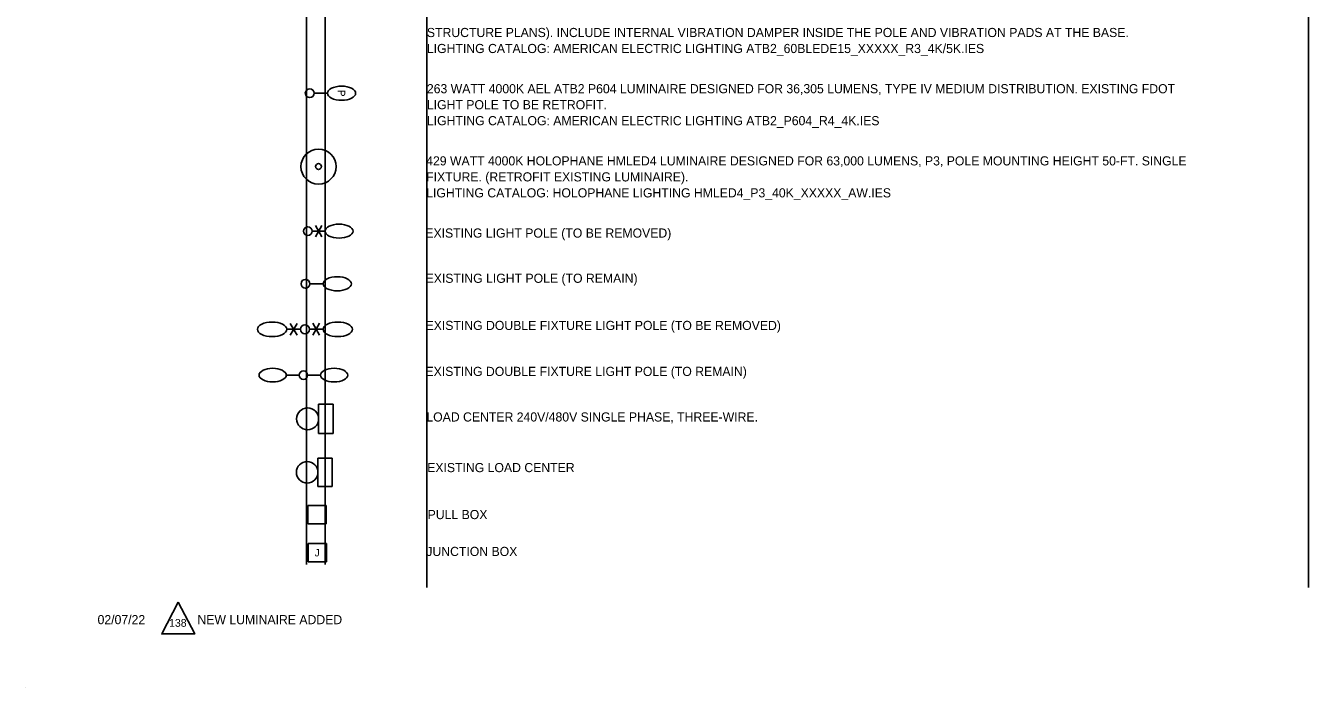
# Model space of a CAD drawing. Extents: x -0.6 to 15.1, y -0.9 to 9.2.
# Drawn here: x -0.55 to 9.27, y -0.9 to 4.17 of the extents above; entities that cross this region are included whole.
import ezdxf

# ---------------------------------------------------------------- set-up
doc = ezdxf.new("R2010")
doc.units = 0
for name, color, linetype in [('ActivePointCell_dp', 7, 'Continuous'), ('AdhocPoint_dp', 7, 'Continuous'), ('Cloud_dp', 7, 'Continuous'), ('JunctBoxA', 7, 'Continuous'), ('LoadCenter', 7, 'Continuous'), ('LoadCenter_ep', 7, 'Continuous'), ('PoleLight', 7, 'Continuous'), ('PoleLight_ep', 7, 'Continuous'), ('PullBox', 7, 'Continuous'), ('TextLabel', 7, 'Continuous'), ('TextMisc', 7, 'Continuous')]:
    doc.layers.add(name, color=color, linetype=linetype)

msp = doc.modelspace()

# ---------------------------------------------------------------- linework, layer by layer
at = {"layer": 'ActivePointCell_dp'}
for p, q in [((2.5213, -0.1347), (2.5213, 8.8406)), ((9.2686, -0.1347), (9.2686, 8.9112)), ((1.7419, 8.8041), (1.7419, 0.0422)), ((1.6003, 8.6424), (1.6003, 0.0422))]:
    msp.add_line(p, q, dxfattribs=at)
at = {"layer": 'AdhocPoint_dp'}
msp.add_line((-0.55, -0.9), (-0.55, -0.9), dxfattribs=at)
at = {"layer": 'Cloud_dp'}
msp.add_lwpolyline([(0.618, -0.2467), (0.4913, -0.4908), (0.7447, -0.4908)], close=True, dxfattribs=at)
at = {"layer": 'LoadCenter'}
for p, q in [((1.6927, 1.0446), (1.6927, 1.2695)), ((1.6927, 1.2695), (1.8051, 1.2695)), ((1.8051, 1.2695), (1.8051, 1.0446)), ((1.8051, 1.0446), (1.6927, 1.0446))]:
    msp.add_line(p, q, dxfattribs=at)
msp.add_circle((1.6083, 1.1571), 0.0843, dxfattribs=at)
at = {"layer": 'LoadCenter_ep'}
for p, q in [((1.6872, 0.6379), (1.6872, 0.8572)), ((1.6872, 0.8572), (1.7968, 0.8572)), ((1.7968, 0.8572), (1.7968, 0.6379)), ((1.7968, 0.6379), (1.6872, 0.6379))]:
    msp.add_line(p, q, dxfattribs=at)
msp.add_circle((1.6049, 0.7476), 0.0822, dxfattribs=at)
at = {"layer": 'PoleLight'}
msp.add_line((1.6584, 3.6517), (1.7598, 3.6517), dxfattribs=at)
for centre, radius in [((1.6246, 3.6517), 0.0338), ((1.6918, 3.0899), 0.1344), ((1.6918, 3.0899), 0.0224)]:
    msp.add_circle(centre, radius, dxfattribs=at)
msp.add_ellipse((1.8679, 3.6517), major_axis=(0.1082, 0), ratio=0.5, dxfattribs=at)
at = {"layer": 'PoleLight_ep'}
for p, q in [((1.6427, 2.5953), (1.7426, 2.5953)), ((1.7176, 2.5521), (1.6677, 2.6386)), ((1.7176, 2.6386), (1.6677, 2.5521)), ((1.6254, 2.192), (1.7268, 2.192)), ((1.4753, 1.7974), (1.5276, 1.8881)), ((1.4753, 1.8881), (1.5276, 1.7974)), ((1.7001, 1.8892), (1.6477, 1.7985)), ((1.7001, 1.7985), (1.6477, 1.8892)), ((1.5528, 1.8433), (1.4481, 1.8433)), ((1.6226, 1.8433), (1.7273, 1.8433)), ((1.5431, 1.492), (1.4451, 1.492)), ((1.6084, 1.492), (1.7063, 1.492))]:
    msp.add_line(p, q, dxfattribs=at)
for centre, radius in [((1.6094, 2.5953), 0.0333), ((1.5916, 2.192), 0.0338), ((1.5877, 1.8433), 0.0349), ((1.5757, 1.492), 0.0326)]:
    msp.add_circle(centre, radius, dxfattribs=at)
for centre, major_axis in [((1.8492, 2.5953), (0.1066, 0)), ((1.835, 2.192), (0.1082, 0)), ((1.3364, 1.8433), (-0.1117, 0)), ((1.839, 1.8433), (0.1117, 0)), ((1.3407, 1.492), (-0.1045, 0)), ((1.8108, 1.492), (0.1045, 0))]:
    msp.add_ellipse(centre, major_axis=major_axis, ratio=0.5, dxfattribs=at)
at = {"layer": 'PullBox'}
for p, q in [((1.6108, 0.3526), (1.6108, 0.4932)), ((1.6108, 0.4932), (1.7514, 0.4932)), ((1.7514, 0.4932), (1.7514, 0.3526)), ((1.7514, 0.3526), (1.6108, 0.3526)), ((1.6115, 0.2018), (1.7522, 0.2018)), ((1.6115, 0.0612), (1.6115, 0.2018)), ((1.7522, 0.2018), (1.7522, 0.0612)), ((1.7522, 0.0612), (1.6115, 0.0612))]:
    msp.add_line(p, q, dxfattribs=at)

# ---------------------------------------------------------------- texts
at = {"layer": 'Cloud_dp'}
msp.add_text('138', height=0.05998, rotation=0, dxfattribs=at).set_placement((0.5481, -0.4358))
at = {"layer": 'JunctBoxA'}
msp.add_text('J', height=0.0563, dxfattribs=at).set_placement((1.6628, 0.1034))
at = {"layer": 'TextLabel'}
msp.add_text('P', height=0.0572, rotation=270.00003, dxfattribs=at).set_placement((1.8393, 3.6775))
at = {"layer": 'TextMisc'}
for s, p in [('STRUCTURE PLANS). INCLUDE INTERNAL VIBRATION DAMPER INSIDE THE POLE AND VIBRATION PADS AT THE BASE.', (2.5213, 4.0821)), ('LIGHTING CATALOG: AMERICAN ELECTRIC LIGHTING ATB2_60BLEDE15_XXXXX_R3_4K/5K.IES', (2.5213, 3.9596)), ('263 WATT 4000K AEL ATB2 P604 LUMINAIRE DESIGNED FOR 36,305 LUMENS, TYPE IV MEDIUM DISTRIBUTION. EXISTING FDOT ', (2.5213, 3.6516)), ('LIGHT POLE TO BE RETROFIT.', (2.5213, 3.5291)), ('LIGHTING CATALOG: AMERICAN ELECTRIC LIGHTING ATB2_P604_R4_4K.IES', (2.5213, 3.4066)), ('429 WATT 4000K HOLOPHANE HMLED4 LUMINAIRE DESIGNED FOR 63,000 LUMENS, P3, POLE MOUNTING HEIGHT 50-FT. SINGLE ', (2.5159, 3.0987)), ('FIXTURE. (RETROFIT EXISTING LUMINAIRE).', (2.5159, 2.9762)), ('LIGHTING CATALOG: HOLOPHANE LIGHTING HMLED4_P3_40K_XXXXX_AW.IES', (2.5159, 2.8537))]:
    msp.add_text(s, height=0.07, dxfattribs=at).set_placement(p)
for s, p in [('EXISTING LIGHT POLE (TO BE REMOVED)', (2.5094, 2.5457)), ('EXISTING LIGHT POLE (TO REMAIN)', (2.5114, 2.1993)), ('EXISTING DOUBLE FIXTURE LIGHT POLE (TO BE REMOVED)', (2.511, 1.8379)), ('EXISTING DOUBLE FIXTURE LIGHT POLE (TO REMAIN)', (2.5104, 1.4857)), ('LOAD CENTER 240V/480V SINGLE PHASE, THREE-WIRE.', (2.5173, 1.1368)), ('EXISTING LOAD CENTER', (2.5236, 0.7489)), ('PULL BOX', (2.5271, 0.389)), ('JUNCTION BOX', (2.5169, 0.1065)), ('02/07/22', (0.0005, -0.4161)), ('NEW LUMINAIRE ADDED', (0.765, -0.4161))]:
    msp.add_text(s, height=0.07, rotation=360, dxfattribs=at).set_placement(p)

doc.saveas('drawing.dxf')
